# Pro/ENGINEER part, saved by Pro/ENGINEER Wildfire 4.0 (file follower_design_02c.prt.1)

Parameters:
  METRIC = "NO"

Other parameters: PITCH, DRILL_DIAMETER, THREAD_DIAMETER, THREADS_PER_INCH, THREAD_DEPTH, THREAD_LENGTH, DRILL_POINT_ANGLE, DRILL_DEPTH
